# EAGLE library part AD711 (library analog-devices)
Precision, Low Cost, High Speed, BiFET Op Amp Source: http://www.analog.com/static/imported-files/data_sheets/AD711.pdf
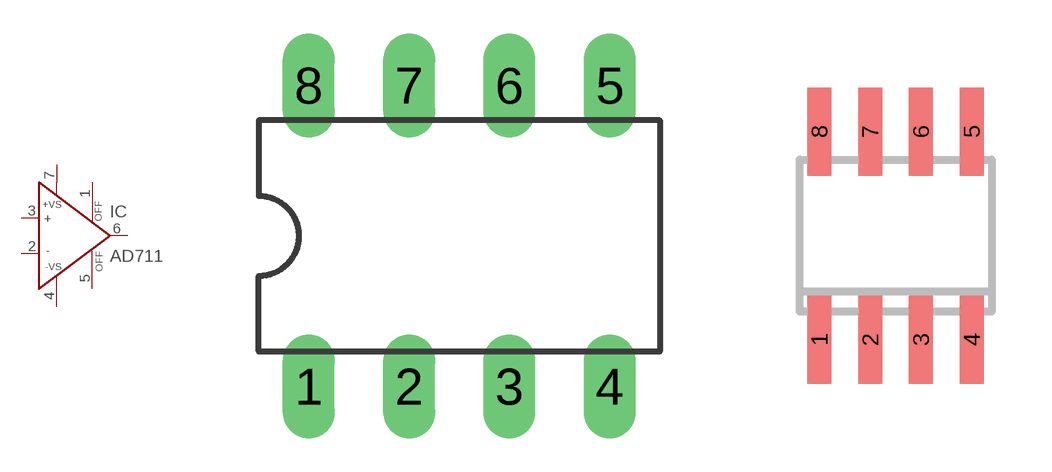
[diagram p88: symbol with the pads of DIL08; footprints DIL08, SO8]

Designator prefix IC

## AD711N (MPN: AD711BQ; OC_FARNELL: 9604839; OC_NEWARK: 66F5826)  [DIL08]
1  OFF  pas
2  IN-  in
3  IN+  in
4  -VS  in
5  OFF  pas
6  OUT  out
7  +VS  in

## AD711RN (MF: ALTERA CORPORATION; MPN: AD711KRZ; OC_FARNELL: 9426396; OC_NEWARK: 59K4541)  [SO8]
Pads as for DIL08

## AD711H (OC_FARNELL: unknown; OC_NEWARK: unknown)  [H08]
Pads as for DIL08

## Footprint DIL08 (pad centres in mm)
Dual In Line Package
drill 0.813 long: 1 -3.81,-3.81; 2 -1.27,-3.81; 3 1.27,-3.81; 4 3.81,-3.81; 5 3.81,3.81; 6 1.27,3.81; 7 -1.27,3.81; 8 -3.81,3.81

## Footprint SO8 (pad centres in mm)
8-Lead Small Outline IC (SO-8) Source: http://www.analog.com/UploadedFiles/Data_Sheets/703465986AD8611_2_0.pdf
smd 0.6 x 2.2: 1 -1.905,-2.6; 2 -0.635,-2.6; 3 0.635,-2.6; 4 1.905,-2.6; 5 1.905,2.6; 6 0.635,2.6; 7 -0.635,2.6; 8 -1.905,2.6

## Footprint H08 (pad centres in mm)
8-Lead Metal Can TO-99 (H-8) Source: http://www.analog.com/static/imported-files/data_sheets/AD711.pdf
drill 0.8 pad 1.3 round: 1 -1.796,-1.796; 2 0,-2.54; 3 1.796,-1.796; 4 2.54,0; 5 1.796,1.796; 6 0,2.54; 7 -1.796,1.796; 8 -2.54,0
